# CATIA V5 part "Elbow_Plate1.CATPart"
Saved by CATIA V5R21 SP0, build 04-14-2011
Part number: Elbow_Plate1
Bounding box of the stored display mesh (mm): x 0 to 3, y -77.993 to -3.639, z -50.993 to 11
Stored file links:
  F:\教程\Robotic_Arm_Arduino_Kinect\机械臂CAD\Arm_Detailed_Design_Assembly\Elbow_Plate1.CATPart
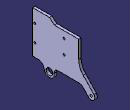
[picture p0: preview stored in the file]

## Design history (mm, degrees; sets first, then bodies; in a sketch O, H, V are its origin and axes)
Body1 (main body)
  DatumCurve1
  Sketch1 on yz-plane, origin (0, 0, 0), H (0, 1, 0), V (0, 0, 1)
    line L1 (-22.9934, 6) -> (-52.0346, 6)
    line L2 (-77.9934, -0.2265) -> (-77.9934, -39)
    line L3 (-48.1954, -39) -> (-22.1954, -39)
    line L4 (-22.9934, -14.8175) -> (-22.9934, 6)
    point P3 (-77.9934, -39)
    point P4 (-23.6185, -38.212)
    circle A1 centre (-57.9934, -45) radius 4
    point P5 (-57.9934, -45)
    arc A2 centre (-57.9934, -45) radius 6 from (-52.1146, -43.8) to (-63.9318, -45.8571) cw
    arc A3 centre (-48.1954, -43) radius 4 from (-52.1146, -43.8) to (-48.1954, -39) cw
    line L5 (-77.9934, -39) -> (-71.8498, -39)
    arc A4 centre (-71.8498, -47) radius 8 from (-63.9318, -45.8571) to (-71.8498, -39) ccw
    circle A5 centre (-7.9934, -45) radius 1.25
    point P12 (-7.9934, -45)
    arc A6 centre (-7.9934, -45) radius 4.3764 from (-4.8145, -41.9921) to (-11.1909, -47.9881) cw
    line L6 (-11.1909, -47.9881) -> (-17.8116, -40.9033)
    line L7 (-4.8145, -41.9921) -> (-17.5208, -28.5636)
    arc A7 centre (-22.1954, -45) radius 6 from (-17.8116, -40.9033) to (-22.1954, -39) ccw
    arc A8 centre (-2.9934, -14.8175) radius 20 from (-17.5208, -28.5636) to (-22.9934, -14.8175) cw
    line L8 (-77.9934, -0.2265) -> (-77.9934, 11)
    line L9 (-77.9934, 11) -> (-57.9934, 11)
    line L10 (-57.9934, 11) -> (-52.0346, 6)
    axis line L11 (-35.8571, 49.2803) -> (-35.8571, -128.5581)
    circle A9 centre (-75.4934, -4) radius 1.25
    point P26 (-75.4934, -4)
    circle A10 centre (-75.4934, -24) radius 1.25
    point P27 (-75.4934, -24)
    circle A11 centre (-40.4934, -2) radius 1.25
    point P28 (-40.4934, -2)
    circle A12 centre (-40.4934, -19) radius 1.25
    point P29 (-40.4934, -19)
    distance L2 L4 = 55
    radius A1 = 4
    radius A2 = 6
    radius A3 = 4
    radius A4 = 8
    distance P5 P12 = 50
    radius A5 = 1.25
    distance P5 H = 45
    distance P12 H = 45
    distance L1 L3 = 45
    radius A7 = 6
    radius A8 = 20
    distance L2 P5 = 20
    length L3 = 26
    distance L9 L5 = 50
    angle L10 L9 = 140
    length L9 = 20
    distance L4 V = 22.9934
    distance P27 L5 = 15
    radius A10 = 1.25
    distance P27 L2 = 2.5
    distance P26 L9 = 15
    distance P26 L8 = 2.5
    radius A9 = 1.25
    distance P28 L8 = 37.5
    radius A11 = 1.25
    distance P28 L1 = 8
    radius A12 = 1.25
    distance P29 L1 = 25
    distance P29 L2 = 37.5
    horizontal: L1 H, L3 H, L9 H
    vertical: L2 V, L4 V, L8 V, L11 V
    tangency: A2 L3, A3 A2, A3 L3, L5 A2, A4 A2, A4 L5, L6 A6, L7 A6, A7 L6, A7 L3, A8 L7, A8 L4
    coincidence: L3 P3
  Pad1: profile Sketch1, direction (1, 0, 0), length 3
